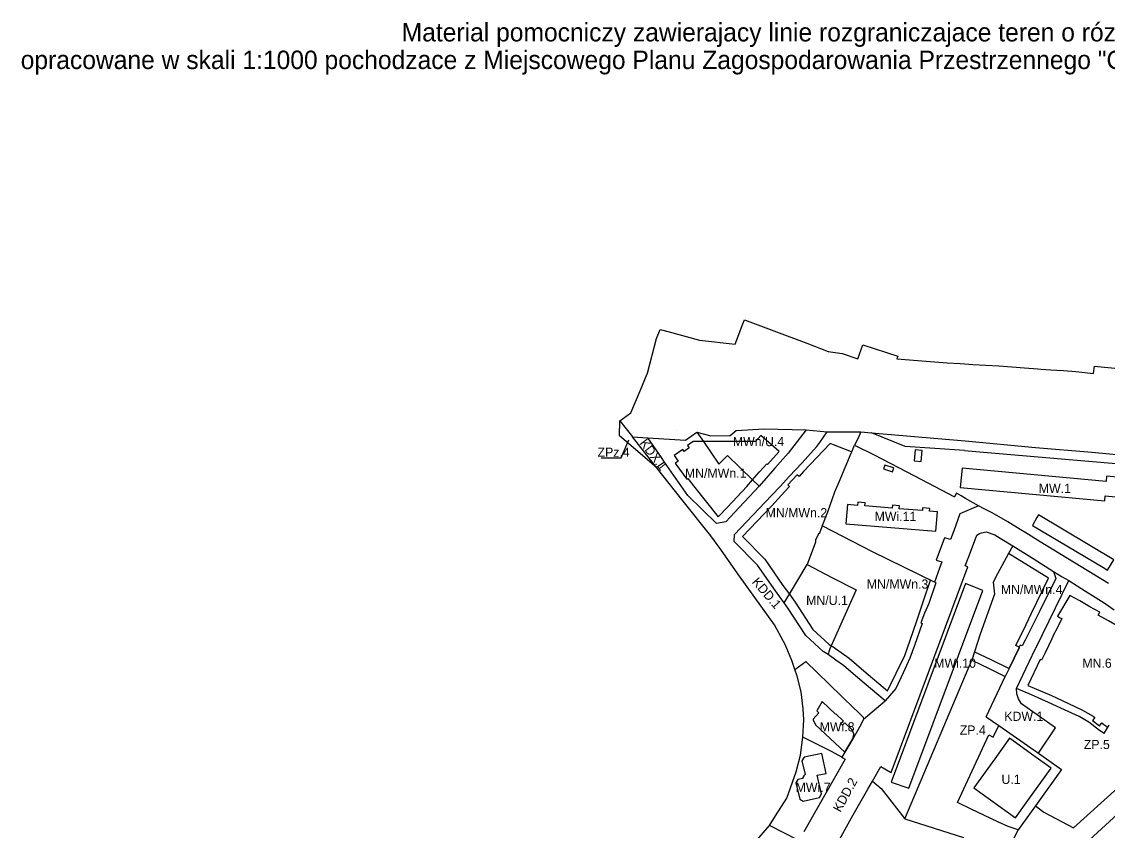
# Model space of a CAD drawing. Extents: x 7425067 to 7426806, y 5549054 to 5550619.
# Drawn here: x 7425067 to 7425657, y 5550180 to 5550619 of the extents above; entities that cross this region are included whole.
import ezdxf

# ---------------------------------------------------------------- set-up
doc = ezdxf.new("R2010")
doc.units = 0
for name, color, linetype in [('__LEGENDA_RAMKA_LOGO_PODZIAŁKA', 7, 'Continuous'), ('LIN_Linia Zabudowy Nieprzekraczalna', 7, 'Continuous'), ('LIN_linia zabudowy obowiązująca', 7, 'Continuous'), ('LIN_linie_rozgraniczajace', 7, 'Continuous'), ('TXT_Oznaczenia_przeznaczen', 7, 'Continuous')]:
    doc.layers.add(name, color=color, linetype=linetype)

msp = doc.modelspace()

# ---------------------------------------------------------------- linework, layer by layer
at = {"layer": 'LIN_Linia Zabudowy Nieprzekraczalna'}
for points in [[(7425478.42, 5550385.57), (7425468.62, 5550394.22), (7425465.6653, 5550390.8799)], [(7425431.81, 5550390.89), (7425428.72, 5550388.71), (7425429.6, 5550387.46), (7425426.96, 5550385.6), (7425426.21, 5550386.67), (7425421.51, 5550383.36), (7425423.7, 5550380.27), (7425422.05, 5550379.1), (7425422.43, 5550378.57)], [(7425465.6653, 5550390.8799), (7425437.3143, 5550390.8884), (7425431.81, 5550390.89)], [(7425506.2635, 5550389.9106), (7425491.79, 5550374.61), (7425489.34, 5550372.02), (7425488.36, 5550372.88), (7425483.12, 5550367.46), (7425484.12, 5550366.45), (7425481.65, 5550363.86), (7425474.25, 5550355.86), (7425458.5894, 5550339.2869)], [(7425471.836, 5550378.8705), (7425472.21, 5550378.54), (7425478.42, 5550385.57)], [(7425517.8765, 5550385.3819), (7425508.06, 5550389.21), (7425506.2635, 5550389.9106)], [(7425422.43, 5550378.57), (7425428.37, 5550370.43), (7425428.8496, 5550370.7798)], [(7425445.4198, 5550350.0654), (7425450.3933, 5550355.2452), (7425460.902, 5550366.6065), (7425464.0359, 5550370.1778), (7425467.8435, 5550374.5168), (7425471.836, 5550378.8705)], [(7425428.8496, 5550370.7798), (7425432.0204, 5550366.8442), (7425445.4198, 5550350.0654)], [(7425458.5894, 5550339.2869), (7425470.6709, 5550327.046), (7425480.5563, 5550312.816), (7425484.0439, 5550308.015), (7425485.3048, 5550306.2793), (7425487.1951, 5550303.6788), (7425496.7725, 5550288.8563), (7425505.5472, 5550280.9177), (7425506.8318, 5550280.0747), (7425507.8585, 5550279.4009), (7425516.544, 5550273.2426), (7425524.3985, 5550266.4796), (7425537.3647, 5550255.5977)], [(7425624.75, 5550316.69), (7425603.1035, 5550330.0661)], [(7425549.71, 5550283), (7425553.29, 5550293.58), (7425556.9, 5550304.42), (7425560.783, 5550315.6364)], [(7425611.3279, 5550288.8219), (7425615.3056, 5550297.3143), (7425624.75, 5550316.69)], [(7425636.35, 5550307.4), (7425629.7, 5550296.11), (7425631.1825, 5550295.2878)], [(7425678.5251, 5550280.9263), (7425678.8, 5550281.4), (7425667.67, 5550287.68), (7425657.41, 5550293.57), (7425651.81, 5550296.72), (7425652.68, 5550298.21), (7425647.29, 5550301.26), (7425641.86, 5550304.43), (7425636.35, 5550307.4)], [(7425631.1825, 5550295.2878), (7425632.0243, 5550294.821), (7425629.31, 5550289.26), (7425627.77, 5550286.31), (7425626.6378, 5550283.8343), (7425623.0566, 5550276.1544), (7425621.0463, 5550272.262), (7425620.3, 5550272.62), (7425613.5251, 5550258.5082)], [(7425607.0736, 5550280.1878), (7425611.2768, 5550288.7156), (7425611.3279, 5550288.8219)], [(7425537.3647, 5550255.5977), (7425546.73, 5550274.84), (7425549.71, 5550283)], [(7425603.46, 5550267.78), (7425606.115, 5550273.355), (7425608.77, 5550278.93), (7425608.9418, 5550279.2992), (7425607.0736, 5550280.1878)], [(7425584.5923, 5550276.762), (7425593.44, 5550272.55), (7425603.46, 5550267.78)], [(7425613.5251, 5550258.5082), (7425617.0526, 5550257.0008)], [(7425617.0526, 5550257.0008), (7425626.4246, 5550252.9612)], [(7425626.4246, 5550252.9612), (7425635.2256, 5550248.8725)], [(7425635.2256, 5550248.8725), (7425643.3462, 5550245.0982)], [(7425643.3462, 5550245.0982), (7425649, 5550241.7939), (7425649.9122, 5550241.0902), (7425648.76, 5550239.42), (7425652.55, 5550236.62), (7425653.6759, 5550238.1865), (7425654.8959, 5550237.2454), (7425657.0714, 5550235.8304)]]:
    msp.add_lwpolyline(points, dxfattribs=at)
at = {"layer": 'LIN_linia zabudowy obowiązująca'}
for points in [[(7425552.37, 5550386.44), (7425551.76, 5550380.45), (7425555.64, 5550380.06), (7425556.25, 5550386.04), (7425552.37, 5550386.44)], [(7425535.93, 5550378.17), (7425535.23, 5550376.09), (7425540.02, 5550374.51), (7425540.73, 5550376.61), (7425535.93, 5550378.17)], [(7425577.83, 5550376.56), (7425576.82, 5550365.9), (7425655.37, 5550358.71), (7425655.64, 5550361.43), (7425687.2, 5550358.45), (7425688.22, 5550369.3), (7425656.31, 5550372.18), (7425656.06, 5550369.17), (7425577.83, 5550376.56)], [(7425515.54, 5550356.69), (7425514.68, 5550346.32), (7425563.64, 5550342.27), (7425564.51, 5550352.72), (7425560.17, 5550353.08), (7425560.3, 5550354.64), (7425556.43, 5550354.96), (7425556.31, 5550353.41), (7425543.63, 5550354.46), (7425543.77, 5550356.11), (7425540.1103, 5550356.4205), (7425539.95, 5550354.74), (7425525.05, 5550355.97), (7425525.19, 5550357.63), (7425521.23, 5550357.96), (7425521.08, 5550356.23)], [(7425521.08, 5550356.23), (7425515.54, 5550356.69)], [(7425656.83, 5550321.15), (7425660.19, 5550326.68), (7425619.2737, 5550351.0673), (7425618.47, 5550349.66), (7425616.02, 5550345.37), (7425654.29, 5550322.64), (7425656.83, 5550321.15)], [(7425579.67, 5550313.76), (7425539.31, 5550206.04), (7425548.94, 5550202.62), (7425589.19, 5550310.12)], [(7425589.19, 5550310.12), (7425579.67, 5550313.76)], [(7425501.89, 5550249.69), (7425498.96, 5550244.69), (7425500.1, 5550243.6), (7425496.97, 5550240.25), (7425496.97, 5550239.8), (7425498.15, 5550237.14), (7425514.17, 5550222.17), (7425518.46, 5550229.54), (7425519.07, 5550231.92), (7425519.01, 5550232.45), (7425517.81, 5550234.77), (7425514.21, 5550238.15), (7425512.91, 5550236.92), (7425512.04, 5550237.8), (7425513.26, 5550239.03), (7425513.41, 5550239.18), (7425509.27, 5550243.05), (7425509.12, 5550242.9), (7425501.89, 5550249.69)], [(7425603.5744, 5550229.8424), (7425595.57, 5550218.67), (7425584.2, 5550202.8)], [(7425626.26, 5550213.58), (7425616.83, 5550220.34), (7425603.5744, 5550229.8424)], [(7425499.23, 5550209.71), (7425503.94, 5550210.72), (7425501.63, 5550221.61), (7425492.08, 5550219.58), (7425490.88, 5550217.51), (7425492.6, 5550210.14), (7425491.94, 5550209.39), (7425491.42, 5550208.58), (7425491.34, 5550208.04)], [(7425491.34, 5550208.04), (7425488.61, 5550207.4), (7425487.52, 5550205.68), (7425489.7, 5550196.74), (7425491.6, 5550195.73), (7425500.41, 5550197.62), (7425501.52, 5550199.61), (7425499.23, 5550209.71)], [(7425606.884, 5550186.5426), (7425613.64, 5550195.97), (7425626.26, 5550213.58)], [(7425584.2, 5550202.8), (7425606.884, 5550186.5426)]]:
    msp.add_lwpolyline(points, dxfattribs=at)
at = {"layer": 'LIN_linie_rozgraniczajace'}
for points in [[(7425458.78, 5550454.77), (7425459.67, 5550457.12)], [(7425459.67, 5550457.12), (7425475.59, 5550451.1)], [(7425411.86, 5550446.97), (7425413.8, 5550451.79)], [(7425413.8, 5550451.79), (7425418.7, 5550450.45)], [(7425418.7, 5550450.45), (7425435.15, 5550445.93)], [(7425454.6, 5550443.83), (7425458.78, 5550454.77)], [(7425475.59, 5550451.1), (7425493.56, 5550444.31)], [(7425407.03, 5550428.05), (7425411.86, 5550446.97)], [(7425435.15, 5550445.93), (7425454.6, 5550443.83)], [(7425493.56, 5550444.31), (7425505.2, 5550439.91)], [(7425505.2, 5550439.91), (7425512.71, 5550438.71)], [(7425512.71, 5550438.71), (7425521.17, 5550435.87)], [(7425521.17, 5550435.87), (7425523.94, 5550443.5)], [(7425523.94, 5550443.5), (7425542.99, 5550437.24)], [(7425542.99, 5550437.24), (7425542.48, 5550435.77)], [(7425542.48, 5550435.77), (7425562.84, 5550434.26)], [(7425562.84, 5550434.26), (7425569.81, 5550433.74)], [(7425569.81, 5550433.74), (7425576.84, 5550433.36)], [(7425576.84, 5550433.36), (7425581.5, 5550432.95)], [(7425581.5, 5550432.95), (7425583.76, 5550432.76)], [(7425583.76, 5550432.76), (7425590.79, 5550432.34)], [(7425405.98, 5550425.56), (7425407.03, 5550428.05)], [(7425590.79, 5550432.34), (7425597.86, 5550432.09)], [(7425597.86, 5550432.09), (7425604.92, 5550431.55)], [(7425604.92, 5550431.55), (7425611.79, 5550431.04)], [(7425611.79, 5550431.04), (7425618.94, 5550430.42)], [(7425618.94, 5550430.42), (7425620.84, 5550430.28)], [(7425620.84, 5550430.28), (7425626.03, 5550429.89)], [(7425626.03, 5550429.89), (7425629.33, 5550429.68)], [(7425629.33, 5550429.68), (7425632.98, 5550429.45)], [(7425632.98, 5550429.45), (7425639.71, 5550429.05)], [(7425639.71, 5550429.05), (7425649.21, 5550427.97)], [(7425649.21, 5550427.97), (7425649.85, 5550431.9)], [(7425649.85, 5550431.9), (7425675.4, 5550429.25)], [(7425402.99, 5550418.52), (7425405.98, 5550425.56)], [(7425397.88, 5550406.59), (7425402.99, 5550418.52)], [(7425391.96, 5550402.24), (7425397.88, 5550406.59)], [(7425391.75, 5550394.04), (7425391.96, 5550402.24)], [(7425391.96, 5550402.24), (7425398.7544, 5550393.5833)], [(7425455.2, 5550396.88), (7425470.39, 5550397.76)], [(7425470.39, 5550397.76), (7425493.23, 5550397.29)], [(7425493.23, 5550397.29), (7425483.3939, 5550384.5693)], [(7425493.23, 5550397.29), (7425504.51, 5550396.19)], [(7425411.96, 5550376.76), (7425391.75, 5550394.04)], [(7425411.96, 5550376.76), (7425398.7544, 5550393.5833)], [(7425398.7544, 5550393.5833), (7425407.1632, 5550393.0351)], [(7425414.57, 5550382.22), (7425407.1632, 5550393.0351)], [(7425407.1632, 5550393.0351), (7425427.64, 5550391.7)], [(7425427.64, 5550391.7), (7425433.7, 5550396.11)], [(7425433.7, 5550396.11), (7425441.35, 5550394.05)], [(7425433.7, 5550396.11), (7425437.3143, 5550390.8884), (7425445.82, 5550378.6), (7425450.38, 5550383.27), (7425464.0359, 5550370.1778), (7425467.58, 5550366.78)], [(7425441.35, 5550394.05), (7425451.97, 5550394.17)], [(7425451.97, 5550394.17), (7425455.2, 5550396.88)], [(7425500.65, 5550390.46), (7425504.51, 5550396.19)], [(7425504.51, 5550396.19), (7425522.89, 5550396.13)], [(7425521.1422, 5550392.4596), (7425519.48, 5550388.99)], [(7425522.89, 5550396.13), (7425521.1422, 5550392.4596)], [(7425522.89, 5550396.13), (7425528.6949, 5550395.6306)], [(7425546.9567, 5550388.2216), (7425528.6949, 5550395.6306)], [(7425528.6949, 5550395.6306), (7425579.61, 5550391.25)], [(7425579.61, 5550391.25), (7425617.65, 5550387.78)], [(7425490.94, 5550379.43), (7425497.15, 5550386.2)], [(7425497.15, 5550386.2), (7425498.9, 5550388.33)], [(7425498.9, 5550388.33), (7425500.65, 5550390.46)], [(7425517.56, 5550384.62), (7425517.8921, 5550385.3758), (7425519.48, 5550388.99)], [(7425519.48, 5550388.99), (7425530.19, 5550383.63)], [(7425579.16, 5550386.05), (7425546.9567, 5550388.2216)], [(7425579.16, 5550386.05), (7425585.24, 5550385.53)], [(7425585.24, 5550385.53), (7425691.07, 5550376.4)], [(7425617.65, 5550387.78), (7425648.39, 5550385.1)], [(7425416.28, 5550379.76), (7425411.96, 5550376.76)], [(7425416.28, 5550379.76), (7425414.57, 5550382.22)], [(7425422.565, 5550370.71), (7425416.28, 5550379.76)], [(7425483.3939, 5550384.5693), (7425476.07, 5550376.52)], [(7425483.91, 5550371.89), (7425490.94, 5550379.43)], [(7425511.13, 5550369.14), (7425517.56, 5550384.62)], [(7425530.19, 5550383.63), (7425551.955, 5550372.23)], [(7425648.39, 5550385.1), (7425667.565, 5550383.43)], [(7425426.3, 5550358.5), (7425411.96, 5550376.76)], [(7425476.07, 5550376.52), (7425467.58, 5550366.78)], [(7425428.85, 5550361.66), (7425422.565, 5550370.71)], [(7425479.16, 5550366.77), (7425483.91, 5550371.89)], [(7425508.79, 5550363.69), (7425511.13, 5550369.14)], [(7425551.955, 5550372.23), (7425573.72, 5550360.83)], [(7425444.5277, 5550346.3785), (7425428.85, 5550361.66)], [(7425467.58, 5550366.78), (7425454.15, 5550352.42)], [(7425454.285, 5550340.4432), (7425474.36, 5550361.64)], [(7425474.36, 5550361.64), (7425479.16, 5550366.77)], [(7425504.91, 5550352.72), (7425508.79, 5550363.69)], [(7425574.8, 5550362.88), (7425573.72, 5550360.83)], [(7425577.28, 5550361.48), (7425574.8, 5550362.88)], [(7425441.42, 5550339.8), (7425426.3, 5550358.5)], [(7425586.7864, 5550356.0161), (7425576.72, 5550351.6)], [(7425579.76, 5550360.08), (7425577.28, 5550361.48)], [(7425586.7864, 5550356.0161), (7425579.76, 5550360.08)], [(7425589.873, 5550354.3085), (7425586.7864, 5550356.0161)], [(7425454.15, 5550352.42), (7425449.4559, 5550347.3308)], [(7425501.93, 5550345.01), (7425504.91, 5550352.72)], [(7425576.72, 5550351.6), (7425573.29, 5550342.5)], [(7425594.24, 5550352.2), (7425589.873, 5550354.3085)], [(7425602.76, 5550347.42), (7425594.24, 5550352.2)], [(7425449.4559, 5550347.3308), (7425444.5277, 5550346.3785)], [(7425501.93, 5550345.01), (7425500.25, 5550340.85)], [(7425502.15, 5550344.93), (7425501.93, 5550345.01)], [(7425529.11, 5550331.13), (7425502.15, 5550344.93)], [(7425609.48, 5550343.2), (7425602.76, 5550347.42)], [(7425446.73, 5550332.24), (7425441.42, 5550339.8)], [(7425454.1358, 5550336.6814), (7425454.285, 5550340.4432)], [(7425499.97, 5550341.13), (7425498.19, 5550337.37)], [(7425500.25, 5550340.85), (7425499.97, 5550341.13)], [(7425568.25, 5550338.71), (7425563.69, 5550326.61)], [(7425571.49, 5550337.69), (7425568.25, 5550338.71)], [(7425573.29, 5550342.5), (7425571.49, 5550337.69)], [(7425581.34, 5550327.93), (7425585.79, 5550340.11)], [(7425585.79, 5550340.11), (7425587.27, 5550341.02)], [(7425587.27, 5550341.02), (7425588.44, 5550341.3)], [(7425588.44, 5550341.3), (7425590.9, 5550341.87)], [(7425590.9, 5550341.87), (7425595.57, 5550340.35)], [(7425595.57, 5550340.35), (7425598.45, 5550338.47)], [(7425598.45, 5550338.47), (7425605.42, 5550334.32)], [(7425612.51, 5550341.36), (7425609.48, 5550343.2)], [(7425620.3342, 5550336.5629), (7425612.51, 5550341.36)], [(7425456.01, 5550319.05), (7425446.73, 5550332.24)], [(7425466.81, 5550323.84), (7425454.1358, 5550336.6814)], [(7425498.32, 5550336.37), (7425493.64, 5550324.13)], [(7425498.19, 5550337.37), (7425498.32, 5550336.37)], [(7425605.42, 5550334.32), (7425603.1035, 5550330.0661), (7425597.11, 5550319.06)], [(7425605.42, 5550334.32), (7425616.45, 5550327.38)], [(7425657.37, 5550313.83), (7425620.3342, 5550336.5629)], [(7425562.82, 5550314.64), (7425529.11, 5550331.13)], [(7425563.69, 5550326.61), (7425566.94, 5550325.57)], [(7425579.55, 5550323.36), (7425581.16, 5550327.56)], [(7425581.16, 5550327.56), (7425581.34, 5550327.93)], [(7425616.45, 5550327.38), (7425627.48, 5550320.44)], [(7425476.48, 5550309.92), (7425466.81, 5550323.84)], [(7425481.26, 5550303.34), (7425484.0439, 5550308.015), (7425493.64, 5550324.13)], [(7425493.64, 5550324.13), (7425507.1636, 5550317.1454)], [(7425560.135, 5550267.005), (7425580.95, 5550322.81)], [(7425565.64, 5550322.13), (7425562.82, 5550314.64)], [(7425566.94, 5550325.57), (7425565.64, 5550322.13)], [(7425580.95, 5550322.81), (7425579.55, 5550323.36)], [(7425627.48, 5550320.44), (7425628.79, 5550316.59)], [(7425627.48, 5550320.44), (7425632.22, 5550317.49)], [(7425469.51, 5550300.49), (7425456.01, 5550319.05)], [(7425507.1636, 5550317.1454), (7425520.34, 5550310.35)], [(7425562.82, 5550314.64), (7425563.63, 5550314.29)], [(7425597.11, 5550319.06), (7425594.68, 5550314.6)], [(7425594.68, 5550314.6), (7425595.53, 5550307.99)], [(7425617.9, 5550278.69), (7425635.75, 5550315.43)], [(7425628.79, 5550316.59), (7425620.03, 5550299.05)], [(7425632.22, 5550317.49), (7425635.75, 5550315.43)], [(7425635.75, 5550315.43), (7425644.82, 5550309.77)], [(7425481.26, 5550303.34), (7425476.48, 5550309.92)], [(7425520.34, 5550310.35), (7425506.8318, 5550280.0747), (7425506.04, 5550278.3)], [(7425563.63, 5550314.29), (7425559.74, 5550303)], [(7425644.82, 5550309.77), (7425650.21, 5550306.42)], [(7425483.07, 5550300.85), (7425481.26, 5550303.34)], [(7425559.74, 5550303), (7425557.4766, 5550297.6558)], [(7425595.53, 5550307.99), (7425587.74, 5550286.34)], [(7425650.21, 5550306.42), (7425655.49, 5550303.07)], [(7425655.49, 5550303.07), (7425660.44, 5550299.57)], [(7425475.98, 5550291.46), (7425469.51, 5550300.49)], [(7425492.93, 5550285.59), (7425483.07, 5550300.85)], [(7425557.4766, 5550297.6558), (7425555.4779, 5550292.4747)], [(7425620.03, 5550299.05), (7425613.53, 5550286.04)], [(7425480.91, 5550282.42), (7425475.98, 5550291.46)], [(7425556.22, 5550292.12), (7425551.93, 5550280.22)], [(7425555.4779, 5550292.4747), (7425556.22, 5550292.12)], [(7425502.48, 5550276.95), (7425492.93, 5550285.59)], [(7425587.74, 5550286.34), (7425584.5923, 5550276.762), (7425583.07, 5550272.13)], [(7425613.53, 5550286.04), (7425612.035, 5550283.02)], [(7425481.67, 5550280.69), (7425480.91, 5550282.42)], [(7425485.47, 5550271.99), (7425481.67, 5550280.69)], [(7425551.93, 5550280.22), (7425549.39, 5550273.22)], [(7425609.43, 5550280.33), (7425608.9418, 5550279.2992), (7425608.77, 5550278.93)], [(7425610.54, 5550280), (7425609.43, 5550280.33)], [(7425612.035, 5550283.02), (7425610.54, 5550280)], [(7425505.04, 5550275.27), (7425502.48, 5550276.95)], [(7425505.54, 5550276.785), (7425505.04, 5550275.27)], [(7425509.25, 5550272.285), (7425505.04, 5550275.27)], [(7425506.04, 5550278.3), (7425505.54, 5550276.785)], [(7425549.39, 5550273.22), (7425545.89, 5550265.34)], [(7425606.115, 5550273.355), (7425603.46, 5550267.78)], [(7425608.77, 5550278.93), (7425606.115, 5550273.355)], [(7425607.39, 5550256.78), (7425617.69, 5550278.5)], [(7425617.69, 5550278.5), (7425617.9, 5550278.69)], [(7425487.05, 5550267.14), (7425485.47, 5550271.99)], [(7425487.05, 5550267.14), (7425493.0315, 5550271.4994)], [(7425493.0315, 5550271.4994), (7425499.17, 5550265.52)], [(7425513.46, 5550269.3), (7425509.25, 5550272.285)], [(7425521.16, 5550262.67), (7425513.46, 5550269.3)], [(7425546.82, 5550186.12), (7425583.07, 5550272.13)], [(7425583.07, 5550272.13), (7425592.58, 5550267.65)], [(7425592.58, 5550267.65), (7425601.33, 5550263.31)], [(7425603.46, 5550267.78), (7425602.395, 5550265.545)], [(7425488.2, 5550263.61), (7425487.05, 5550267.14)], [(7425490.48, 5550255.05), (7425488.2, 5550263.61)], [(7425499.17, 5550265.52), (7425519.32, 5550246.02)], [(7425536.09, 5550250.14), (7425521.16, 5550262.67)], [(7425539.32, 5550211.2), (7425560.135, 5550267.005)], [(7425545.89, 5550265.34), (7425541.81, 5550256.915)], [(7425590.9198, 5550241.4411), (7425601.33, 5550263.31)], [(7425602.395, 5550265.545), (7425601.33, 5550263.31)], [(7425541.81, 5550256.915), (7425536.09, 5550250.14)], [(7425615.475, 5550253.325), (7425607.39, 5550256.78)], [(7425607.5921, 5550253.942), (7425607.39, 5550256.78)], [(7425491.51, 5550245.77), (7425490.48, 5550255.05)], [(7425524.2373, 5550240.1602), (7425536.09, 5550250.14)], [(7425608.4709, 5550251.1591), (7425607.5921, 5550253.942)], [(7425610.0997, 5550248.5541), (7425608.4709, 5550251.1591)], [(7425624.79, 5550249.31), (7425615.475, 5550253.325)], [(7425491.83, 5550239.85), (7425491.51, 5550245.77)], [(7425519.32, 5550246.02), (7425520.8, 5550244.57)], [(7425520.8, 5550244.57), (7425524.06, 5550241.21)], [(7425628.628, 5550235.506), (7425610.0997, 5550248.5541)], [(7425633.54, 5550245.245), (7425624.79, 5550249.31)], [(7425641.49, 5550241.55), (7425633.54, 5550245.245)], [(7425491.33, 5550230.38), (7425491.83, 5550239.85)], [(7425524.2373, 5550240.1602), (7425522.8003, 5550237.1186)], [(7425524.06, 5550241.21), (7425524.2373, 5550240.1602)], [(7425590.9198, 5550241.4411), (7425597.7402, 5550236.7061)], [(7425646.76, 5550238.47), (7425641.49, 5550241.55)], [(7425652.58, 5550233.98), (7425646.76, 5550238.47)], [(7425522.8003, 5550237.1186), (7425518.46, 5550229.54)], [(7425594.75, 5550230.46), (7425597.7402, 5550236.7061)], [(7425597.7402, 5550236.7061), (7425619.356, 5550221.6997)], [(7425619.356, 5550221.6997), (7425628.628, 5550235.506)], [(7425655.04, 5550232.38), (7425652.58, 5550233.98)], [(7425655.04, 5550232.38), (7425657.0714, 5550235.8304), (7425657.79, 5550237.05)], [(7425490.14, 5550220.59), (7425491.33, 5550230.38)], [(7425506.93, 5550222.57), (7425491.33, 5550230.38)], [(7425518.46, 5550229.54), (7425514.17, 5550222.17)], [(7425575.33, 5550194.86), (7425592.33, 5550231.6)], [(7425592.33, 5550231.6), (7425594.75, 5550230.46)], [(7425487.8, 5550211.58), (7425490.14, 5550220.59)], [(7425512.4781, 5550219.4766), (7425506.93, 5550222.57)], [(7425514.17, 5550222.17), (7425512.4781, 5550219.4766)], [(7425619.356, 5550221.6997), (7425631.89, 5550212.88)], [(7425514.36, 5550218.44), (7425491.87, 5550178.96)], [(7425512.4781, 5550219.4766), (7425513.01, 5550219.18)], [(7425513.01, 5550219.18), (7425514.36, 5550218.44)], [(7425529.21, 5550206.55), (7425533.74, 5550214.39)], [(7425533.74, 5550214.39), (7425538.89, 5550211.45)], [(7425482.67, 5550197.35), (7425487.8, 5550211.58)], [(7425538.89, 5550211.45), (7425539.32, 5550211.2)], [(7425631.89, 5550212.88), (7425617.6485, 5550193.0469), (7425608.28, 5550180)], [(7425638.3977, 5550181.1426), (7425669.9439, 5550209.5582)], [(7425526.73, 5550202.24), (7425529.21, 5550206.55)], [(7425529.21, 5550206.55), (7425533.88, 5550202.6)], [(7425533.88, 5550202.6), (7425546.82, 5550186.12)], [(7425625.3385, 5550154.8249), (7425677.4704, 5550202.5629)], [(7425476.52, 5550187.63), (7425482.67, 5550197.35)], [(7425518.66, 5550188.28), (7425526.73, 5550202.24)], [(7425582.81, 5550191.31), (7425575.33, 5550194.86)], [(7425597.18, 5550184.35), (7425582.81, 5550191.31)], [(7425617.6485, 5550193.0469), (7425619.25, 5550192.05), (7425622.3265, 5550189.7024), (7425638.3977, 5550181.1426)], [(7425473.21, 5550182.39), (7425476.52, 5550187.63)], [(7425510.365, 5550173.23), (7425518.66, 5550188.28)], [(7425546.82, 5550186.12), (7425578.62, 5550175.9)], [(7425464.15, 5550171.97), (7425473.21, 5550182.39)], [(7425489.2647, 5550174.2827), (7425473.21, 5550182.39)], [(7425602.94, 5550181.88), (7425597.18, 5550184.35)], [(7425608.28, 5550180), (7425600.2936, 5550164.604)], [(7425608.28, 5550180), (7425602.94, 5550181.88)]]:
    msp.add_lwpolyline(points, dxfattribs=at)
at = {"layer": 'TXT_Oznaczenia_przeznaczen'}
msp.add_line((7425422.6977, 5550397.1565), (7425422.6977, 5550397.1565), dxfattribs=at)
msp.add_lwpolyline([(7425381.8196, 5550382.0042), (7425392.7245, 5550382.0042), (7425396.8696, 5550391.7895)], dxfattribs=at)

# ---------------------------------------------------------------- texts
at = {"layer": '__LEGENDA_RAMKA_LOGO_PODZIAŁKA'}
for s, p in [('Material pomocniczy zawierajacy linie rozgraniczajace teren o róznym przeznaczeniu i róznych warunkach zagospodarowania terenu, ', (7425273.469, 5550608.2172)), ('opracowane w skali 1:1000 pochodzace z Miejscowego Planu Zagospodarowania Przestrzennego "Olsza" zatwierdzonego uchwala RMK Nr XXVII/613/19 z dnia 23 pazdziernika 2019r.', (7425066.5281, 5550593.2172))]:
    msp.add_text(s, height=10, dxfattribs=at).set_placement(p)
at = {"layer": 'TXT_Oznaczenia_przeznaczen'}
for s, rotation, p in [('KDX.1', 307.606627, (7425402.4144, 5550389.9599)), ('KDD.1', 310.9259307, (7425463.4327, 5550314.4696)), ('KDD.2', 61.3233078, (7425511.7679, 5550189.2779))]:
    msp.add_text(s, height=5, rotation=rotation, dxfattribs=at).set_placement(p)
for s, p in [('MWn/U.4', (7425453.359, 5550388.4435)), ('ZPz.4', (7425379.8612, 5550382.6599)), ('MN/MWn.1', (7425427.2922, 5550371.2912)), ('MW.1', (7425619.5088, 5550362.9823)), ('MN/MWn.2', (7425471.1406, 5550349.7754)), ('MWi.11', (7425530.3327, 5550347.7991)), ('MN/MWn.3', (7425526.0941, 5550311.0501)), ('MN/MWn.4', (7425598.917, 5550308.0893)), ('MN/U.1', (7425493.1518, 5550302.1993)), ('MWi.10', (7425562.731, 5550268.0918)), ('MN.6', (7425643.145, 5550268.0835)), ('KDW.1', (7425600.7948, 5550239.2416)), ('MWi.8', (7425500.4995, 5550233.5155)), ('ZP.4', (7425576.5855, 5550231.7643)), ('ZP.5', (7425643.9631, 5550223.9449)), ('U.1', (7425599.2549, 5550205.013)), ('MWi.7', (7425487.4446, 5550200.6053))]:
    msp.add_text(s, height=5, dxfattribs=at).set_placement(p)

doc.saveas('drawing.dxf')
